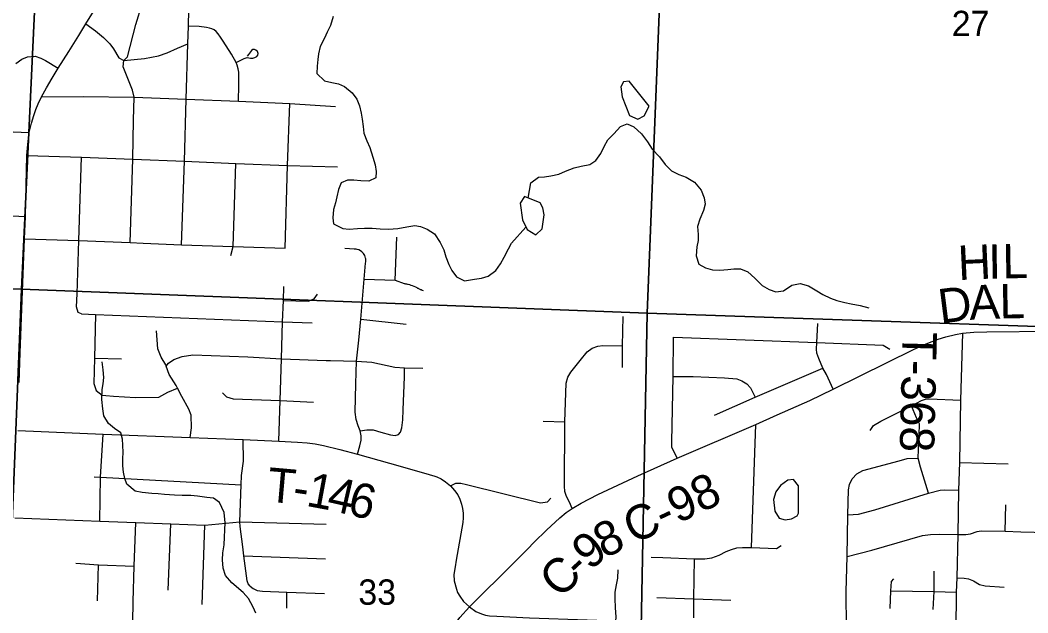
# Model space of a CAD drawing. Extents: x 0 to 34, y 0 to 22.
# Drawn here: x 5.169 to 6.833, y 15.396 to 16.375 of the extents above; entities that cross this region are included whole.
import ezdxf

# ---------------------------------------------------------------- set-up
doc = ezdxf.new("R2010")
doc.units = 0
for name, color, linetype in [('GM_X_Corporation', 7, 'Continuous'), ('GM_X_County_Road', 7, 'Continuous'), ('GM_X_County_Road_Text', 7, 'Continuous'), ('GM_X_Minor_Lake', 7, 'Continuous'), ('GM_X_Minor_River', 7, 'Continuous'), ('GM_X_Section_Text', 7, 'Continuous'), ('GM_X_State_Route', 7, 'Continuous'), ('GM_X_Township_Road', 7, 'Continuous'), ('GM_X_Township_Road_Text', 7, 'Continuous')]:
    doc.layers.add(name, color=color, linetype=linetype)

msp = doc.modelspace()

# ---------------------------------------------------------------- linework, layer by layer
at = {"layer": 'GM_X_Corporation'}
for points in [[(5.2034, 16.9522), (5.1967, 16.4715), (5.1712, 15.9307), (4.1402, 15.964), (4.1823, 16.9818)], [(5.2034, 16.9522), (6.2453, 16.9071), (6.2042, 15.8911), (5.1712, 15.9307), (5.1967, 16.4715)], [(6.2453, 16.9071), (7.2756, 16.8704), (7.2356, 15.8559), (6.2042, 15.8911)], [(4.1402, 15.964), (5.1712, 15.9307), (5.1298, 14.9148), (4.1106, 14.9455)], [(5.1712, 15.9307), (6.2042, 15.8911), (6.1854, 14.88), (5.1298, 14.9148)], [(6.2042, 15.8911), (7.2356, 15.8559), (7.2089, 14.8416), (6.1854, 14.88)]]:
    msp.add_lwpolyline(points, close=True, dxfattribs=at)
at = {"layer": 'GM_X_County_Road'}
for points in [[(6.0179, 15.5128), (6.0381, 15.533), (6.0601, 15.5533), (6.0709, 15.562), (6.0807, 15.5687), (6.0954, 15.5774), (6.1227, 15.5914), (6.1891, 15.6225), (6.2539, 15.6514), (6.384, 15.7073), (6.419, 15.723), (6.4731, 15.7469), (6.5116, 15.7654), (6.6441, 15.8309), (6.6651, 15.8404), (6.6847, 15.8483), (6.6979, 15.8522), (6.7138, 15.8561), (6.7251, 15.858), (6.7436, 15.8597), (6.7654, 15.8605), (6.8727, 15.8614)], [(5.6145, 15.1191), (5.6175, 15.1203), (5.6338, 15.126), (5.6814, 15.1424), (5.732, 15.1595), (5.7488, 15.1661), (5.7643, 15.1736), (5.7818, 15.1854), (5.7952, 15.1976), (5.8068, 15.212), (5.8129, 15.2215), (5.8193, 15.2329), (5.8302, 15.2613), (5.8476, 15.3063), (5.856, 15.3274), (5.865, 15.3452), (5.879, 15.367), (5.8949, 15.3886), (5.9111, 15.406), (5.9846, 15.4793), (6.0068, 15.5016), (6.0179, 15.5128)], [(5.9111, 15.406), (5.9217, 15.3983), (5.931, 15.3945), (5.9376, 15.3927), (5.9443, 15.3913), (5.9561, 15.3908), (6.0101, 15.3883), (6.2004, 15.3814), (6.2816, 15.3786), (6.4091, 15.3749), (6.5336, 15.3708), (6.6147, 15.3683), (6.6506, 15.3674), (6.6923, 15.3658), (6.7048, 15.3649), (6.7136, 15.3641), (6.7227, 15.3622), (6.7349, 15.3585), (6.761, 15.3495), (6.8267, 15.3266), (6.891, 15.3044)]]:
    msp.add_lwpolyline(points, dxfattribs=at)
at = {"layer": 'GM_X_Minor_Lake'}
for points in [[(6.1747, 16.274), (6.1652, 16.2731), (6.1611, 16.2647), (6.1629, 16.2484), (6.1754, 16.2174), (6.1892, 16.2111), (6.1997, 16.2166), (6.2079, 16.2327)], [(6.2079, 16.2327), (6.1747, 16.274)], [(6.0016, 16.0835), (5.9946, 16.0728), (5.9983, 16.0451), (6.0062, 16.0292), (6.0203, 16.0203), (6.0308, 16.0303), (6.0343, 16.0536), (6.0322, 16.0649), (6.0276, 16.0732)], [(6.0276, 16.0732), (6.0016, 16.0835)], [(6.4542, 15.6062), (6.4461, 15.6167), (6.4366, 15.6154), (6.4246, 15.6065), (6.4168, 15.5962), (6.4132, 15.5836), (6.415, 15.5639), (6.4223, 15.5526), (6.4322, 15.55), (6.4428, 15.5517), (6.4519, 15.5564), (6.4545, 15.561)], [(6.4545, 15.561), (6.4542, 15.6062)]]:
    msp.add_lwpolyline(points, dxfattribs=at)
at = {"layer": 'GM_X_Minor_River'}
for points in [[(5.6858, 16.3807), (5.6814, 16.3662), (5.6762, 16.3552), (5.6718, 16.3452), (5.6644, 16.3314), (5.6616, 16.3192), (5.6605, 16.3097), (5.6592, 16.2991), (5.659, 16.2869), (5.6716, 16.2749), (5.6838, 16.2717), (5.6945, 16.2699), (5.7044, 16.2651), (5.7171, 16.255), (5.7252, 16.2441), (5.7291, 16.2332), (5.7319, 16.2214), (5.7336, 16.2116), (5.7353, 16.1991), (5.7366, 16.1881), (5.7413, 16.1756), (5.7467, 16.1643), (5.7515, 16.1484), (5.7551, 16.1359), (5.7568, 16.1249), (5.7561, 16.1146), (5.7445, 16.1091), (5.7315, 16.1097), (5.7202, 16.1107), (5.7095, 16.1109), (5.699, 16.1062), (5.6949, 16.0955), (5.6917, 16.083), (5.6896, 16.073), (5.6863, 16.0624), (5.6853, 16.0483), (5.6862, 16.0384), (5.7019, 16.031), (5.7125, 16.0297), (5.7258, 16.0306), (5.7375, 16.0315), (5.7501, 16.0313), (5.7637, 16.0304), (5.777, 16.0298), (5.7926, 16.0308), (5.8073, 16.0337), (5.8206, 16.0358), (5.8301, 16.0344), (5.8411, 16.0296), (5.853, 16.0218), (5.8627, 16.0078), (5.8685, 15.9954), (5.8717, 15.984), (5.8768, 15.9716), (5.8819, 15.9614), (5.8896, 15.9509), (5.903, 15.9442), (5.9193, 15.9471), (5.9306, 15.9491), (5.942, 15.952), (5.9547, 15.9616), (5.9622, 15.9724), (5.9685, 15.9835), (5.9755, 15.9973), (5.9803, 16.0068), (6.0043, 16.033)], [(6.0078, 16.081), (6.0123, 16.1061), (6.0251, 16.1158), (6.0349, 16.1163), (6.0455, 16.1176), (6.0588, 16.1208), (6.0697, 16.1255), (6.0841, 16.131), (6.0954, 16.1335), (6.1098, 16.1367), (6.1195, 16.1433), (6.1277, 16.1548), (6.1336, 16.1663), (6.1396, 16.177), (6.1493, 16.187), (6.1605, 16.199), (6.1715, 16.2037), (6.1825, 16.1989), (6.1948, 16.1873), (6.2052, 16.1741), (6.2126, 16.1617), (6.2246, 16.149), (6.2342, 16.1365), (6.2446, 16.1261), (6.2568, 16.1201), (6.2686, 16.1154), (6.2828, 16.1072), (6.2936, 16.0944), (6.2983, 16.0816), (6.3, 16.071), (6.2974, 16.0603), (6.2912, 16.0465), (6.2876, 16.034), (6.2889, 16.0207), (6.2886, 16.0108), (6.2865, 16.0005), (6.2856, 15.9857), (6.2899, 15.9721), (6.301, 15.9658), (6.3124, 15.9625), (6.3242, 15.9623), (6.3375, 15.9632), (6.3477, 15.9645), (6.3583, 15.9643), (6.3709, 15.9595), (6.382, 15.949), (6.3943, 15.9367), (6.4058, 15.9304), (6.4169, 15.9263), (6.4294, 15.928), (6.4433, 15.9374), (6.4569, 15.9398), (6.471, 15.9362), (6.4844, 15.9277), (6.4947, 15.9221), (6.5073, 15.9158), (6.5176, 15.9122), (6.5309, 15.9086), (6.5412, 15.9064), (6.556, 15.9036), (6.5705, 15.9)], [(5.3379, 15.6828), (5.3351, 15.6934), (5.3247, 15.7009), (5.3148, 15.7087), (5.3074, 15.7215), (5.3053, 15.7333), (5.304, 15.7485), (5.3045, 15.7648), (5.3059, 15.7743), (5.3069, 15.785), (5.306, 15.7975), (5.3043, 15.8108)], [(5.558, 15.3957), (5.5537, 15.4059), (5.5463, 15.4198), (5.5371, 15.4299), (5.5186, 15.4456), (5.5079, 15.458), (5.5043, 15.4701), (5.5033, 15.4838), (5.5036, 15.4956), (5.5057, 15.5085), (5.5066, 15.5215), (5.5072, 15.5336), (5.5074, 15.545), (5.5057, 15.5617), (5.4983, 15.5783), (5.4883, 15.5854), (5.4773, 15.5868), (5.4621, 15.5888), (5.4507, 15.5898), (5.4363, 15.59), (5.4237, 15.5906), (5.4074, 15.5919), (5.3968, 15.5925), (5.3865, 15.5935), (5.3702, 15.5948), (5.3588, 15.5973), (5.3453, 15.6085), (5.3418, 15.6183), (5.3394, 15.6285), (5.3385, 15.6392), (5.3387, 15.6513), (5.3389, 15.6612), (5.3388, 15.673), (5.3379, 15.6828)], [(6.1557, 15.4671), (6.1555, 15.4534), (6.153, 15.4428), (6.1509, 15.4302), (6.151, 15.4196), (6.1516, 15.4051), (6.1529, 15.3892), (6.1516, 15.3774), (6.1449, 15.3655), (6.139, 15.3552), (6.1338, 15.3449), (6.1268, 15.3296), (6.122, 15.3189), (6.1165, 15.3078), (6.1075, 15.2947), (6.102, 15.2829)]]:
    msp.add_lwpolyline(points, dxfattribs=at)
at = {"layer": 'GM_X_State_Route'}
for points in [[(5.2042, 16.248), (5.2124, 16.2632), (5.2218, 16.279), (5.232, 16.2955), (5.2494, 16.3232), (5.2656, 16.3495), (5.2775, 16.3685), (5.2957, 16.3977), (5.3131, 16.4252)], [(5.184, 16.1896), (5.1875, 16.2049), (5.1913, 16.2175), (5.1948, 16.2275), (5.1987, 16.2366), (5.2042, 16.248)], [(5.1676, 15.7767), (5.1692, 15.8253), (5.1762, 16.0139), (5.1776, 16.0509), (5.1788, 16.1018), (5.1802, 16.1511), (5.1815, 16.1697), (5.184, 16.1896)]]:
    msp.add_lwpolyline(points, dxfattribs=at)
at = {"layer": 'GM_X_Township_Road'}
for p, q in [((5.7884, 15.9456), (5.7912, 16.0163)), ((5.7313, 15.8809), (5.8066, 15.873)), ((5.2918, 15.8169), (5.3362, 15.8157)), ((6.0328, 15.713), (6.0686, 15.7119)), ((6.3766, 15.5042), (6.384, 15.7073)), ((6.7201, 15.6445), (6.8007, 15.6421)), ((6.7956, 15.5311), (6.7965, 15.5746)), ((5.4134, 15.4336), (5.4176, 15.543)), ((5.4697, 15.4103), (5.4737, 15.5412)), ((5.5386, 15.4905), (5.6732, 15.4857)), ((5.2966, 15.4163), (5.2982, 15.4757)), ((5.6091, 15.4039), (5.6094, 15.4303))]:
    msp.add_line(p, q, dxfattribs=at)
for points in [[(5.3507, 16.0076), (5.3553, 16.1451), (5.3563, 16.2096), (5.3572, 16.2474), (5.3546, 16.2591), (5.3391, 16.298), (5.34, 16.3082), (5.3463, 16.3143), (5.3602, 16.3677), (5.3704, 16.4019), (5.3755, 16.4227)], [(5.4354, 16.004), (5.4403, 16.1421), (5.443, 16.2442), (5.4461, 16.336), (5.4472, 16.365), (5.4481, 16.4191)], [(5.2775, 16.3685), (5.2932, 16.3573), (5.3066, 16.346), (5.3168, 16.3358), (5.3232, 16.3275), (5.3319, 16.3124), (5.34, 16.3082), (5.3744, 16.3117), (5.3973, 16.3158), (5.4116, 16.3207), (5.4288, 16.3288), (5.4461, 16.336)], [(5.5295, 16.2411), (5.5299, 16.2674), (5.5299, 16.2836), (5.5299, 16.289), (5.529, 16.2943), (5.5275, 16.3003), (5.5257, 16.3048), (5.5181, 16.3184), (5.5043, 16.3402), (5.4998, 16.3467), (5.4958, 16.352), (5.4925, 16.356), (5.4894, 16.3587), (5.4856, 16.3607), (5.4818, 16.3618), (5.4767, 16.3627), (5.4646, 16.3643), (5.4472, 16.365)], [(5.5257, 16.3048), (5.5391, 16.3113), (5.544, 16.3133), (5.5493, 16.3121), (5.5531, 16.3121), (5.5564, 16.313), (5.5598, 16.315), (5.5616, 16.3168), (5.5622, 16.3195), (5.5609, 16.3228), (5.5582, 16.3255), (5.5558, 16.3266), (5.5533, 16.3262), (5.5511, 16.3246), (5.546, 16.3182), (5.5437, 16.3155)], [(5.1619, 16.3032), (5.1718, 16.3106), (5.1813, 16.3145), (5.1937, 16.3154), (5.2029, 16.3123), (5.211, 16.3084), (5.232, 16.2955)], [(5.184, 16.1896), (5.1875, 16.2049), (5.1913, 16.2175), (5.1948, 16.2275), (5.1987, 16.2366), (5.2042, 16.248)], [(5.2042, 16.248), (5.273, 16.2486), (5.3572, 16.2474), (5.443, 16.2442), (5.5295, 16.2411), (5.6142, 16.2373), (5.6898, 16.2323)], [(5.6066, 15.9982), (5.6105, 16.1348), (5.6142, 16.2373)], [(4.8845, 16.1241), (4.905, 16.1424), (4.916, 16.1538), (4.9265, 16.1653), (4.951, 16.1905), (4.955, 16.1972), (4.9619, 16.1976), (4.9689, 16.1973), (5.0315, 16.1959), (5.1039, 16.1925), (5.184, 16.1896)], [(5.1802, 16.1511), (5.27, 16.1484), (5.3553, 16.1451), (5.4403, 16.1421), (5.5251, 16.1383), (5.6105, 16.1348), (5.693, 16.1327)], [(5.2629, 15.9231), (5.2661, 16.0108), (5.27, 16.1484)], [(5.5167, 15.9863), (5.5206, 16.0011), (5.5251, 16.1383)], [(4.1199, 16.0878), (4.1661, 16.0886), (4.1847, 16.088), (4.2029, 16.0866), (4.2216, 16.0857), (4.2477, 16.0847), (4.2773, 16.084), (4.3004, 16.0838), (4.3544, 16.0828), (4.3818, 16.0818), (4.4203, 16.08), (4.454, 16.0785), (4.5131, 16.0767), (4.6153, 16.0736), (4.6616, 16.0717), (4.7043, 16.07), (4.736, 16.0686), (4.7389, 16.0685), (4.871, 16.0627), (4.9372, 16.0603), (5.0261, 16.0572), (5.1006, 16.0545), (5.1776, 16.0509)], [(5.1762, 16.0139), (5.2661, 16.0108), (5.3507, 16.0076), (5.3722, 16.0066)], [(5.3722, 16.0066), (5.4354, 16.004), (5.5206, 16.0011), (5.6066, 15.9982)], [(5.7261, 15.6583), (5.7299, 15.672), (5.7319, 15.6813), (5.7321, 15.6883), (5.7307, 15.697), (5.727, 15.7051), (5.7236, 15.7156), (5.722, 15.7276), (5.7235, 15.7745), (5.7246, 15.8118), (5.7283, 15.8464), (5.7313, 15.8809), (5.7371, 15.947), (5.7394, 15.9738), (5.7398, 15.9757), (5.7399, 15.9775), (5.7399, 15.9791), (5.7397, 15.9808), (5.7394, 15.9821), (5.7389, 15.9842), (5.738, 15.9862), (5.7371, 15.9879), (5.736, 15.9895), (5.7349, 15.9907), (5.7333, 15.9923), (5.731, 15.994), (5.7283, 15.9954), (5.7257, 15.9961), (5.7236, 15.9965), (5.7207, 15.9969), (5.7049, 15.9979)], [(5.7371, 15.947), (5.7884, 15.9456), (5.803, 15.94), (5.8042, 15.9399), (5.8054, 15.9397), (5.8068, 15.9394), (5.8085, 15.9391), (5.8099, 15.9388), (5.8121, 15.9382), (5.8143, 15.9375), (5.8166, 15.9367), (5.8191, 15.9356), (5.8216, 15.9345), (5.8239, 15.9332), (5.8245, 15.9329), (5.8252, 15.9325), (5.8261, 15.9321), (5.827, 15.9316), (5.828, 15.9312), (5.8289, 15.9308), (5.8298, 15.9304), (5.8311, 15.9299), (5.8329, 15.9292), (5.8346, 15.9287)], [(5.5959, 15.68), (5.5981, 15.7466), (5.6006, 15.8159), (5.6022, 15.877), (5.6037, 15.9118), (5.6043, 15.9352)], [(5.2704, 15.8899), (5.2647, 15.892), (5.2621, 15.9015), (5.2629, 15.9231)], [(5.6037, 15.9118), (5.6447, 15.9107), (5.6544, 15.9148), (5.6599, 15.9224)], [(5.2704, 15.8899), (5.2935, 15.8889), (5.6022, 15.877), (5.6511, 15.8751)], [(5.2935, 15.8889), (5.2918, 15.8169), (5.2905, 15.7749), (5.2945, 15.7633), (5.3045, 15.7554), (5.3105, 15.7551), (5.3232, 15.7541), (5.3592, 15.752), (5.3982, 15.7522), (5.413, 15.7604), (5.4288, 15.767)], [(6.1639, 15.8015), (6.1636, 15.8371), (6.165, 15.8853)], [(5.4499, 15.6856), (5.4519, 15.7019), (5.4512, 15.7228), (5.4474, 15.7326), (5.4362, 15.7532), (5.4288, 15.767), (5.4264, 15.7714), (5.4151, 15.79), (5.4103, 15.8037), (5.4095, 15.8059), (5.402, 15.8185), (5.3964, 15.8322), (5.3943, 15.8619)], [(6.5116, 15.7654), (6.5004, 15.79), (6.4947, 15.8001), (6.4877, 15.8161), (6.4847, 15.8248), (6.4841, 15.8315), (6.4847, 15.8424), (6.4861, 15.8738)], [(6.2539, 15.6514), (6.2451, 15.6698), (6.2449, 15.6785), (6.2471, 15.7867), (6.2477, 15.8516)], [(6.2477, 15.8516), (6.4847, 15.8424), (6.5939, 15.8382), (6.6054, 15.8318)], [(6.7251, 15.858), (6.722, 15.7474), (6.7201, 15.6445), (6.7187, 15.5989), (6.7172, 15.5257), (6.7156, 15.4542), (6.7149, 15.4305), (6.7145, 15.4107), (6.7136, 15.3641)], [(6.0807, 15.5687), (6.0762, 15.5788), (6.0714, 15.5886), (6.0686, 15.5967), (6.0678, 15.6057), (6.0686, 15.7119), (6.0709, 15.7757), (6.0734, 15.7855), (6.0782, 15.7939), (6.0936, 15.8127), (6.1056, 15.827), (6.1135, 15.8334), (6.123, 15.8365), (6.1314, 15.8374), (6.1636, 15.8371)], [(5.4103, 15.8037), (5.4138, 15.8083), (5.4227, 15.8144), (5.4364, 15.8197), (5.4539, 15.822), (5.545, 15.8189), (5.6006, 15.8159), (5.6744, 15.813), (5.6816, 15.8128)], [(5.6816, 15.8128), (5.7246, 15.8118), (5.75, 15.8099), (5.7878, 15.8018), (5.8036, 15.801), (5.8342, 15.8002)], [(5.7307, 15.697), (5.7414, 15.6987), (5.7517, 15.6982), (5.7647, 15.6947), (5.7807, 15.6902), (5.7882, 15.689), (5.7938, 15.6908), (5.7969, 15.6945), (5.7991, 15.7015), (5.8009, 15.7151), (5.8016, 15.7315), (5.8034, 15.786), (5.8036, 15.801)], [(6.3157, 15.7225), (6.3827, 15.7525), (6.4947, 15.8001)], [(6.2471, 15.7867), (6.2802, 15.7864), (6.3323, 15.7841), (6.3527, 15.7827), (6.3606, 15.7796), (6.3692, 15.7746), (6.3748, 15.7679), (6.3827, 15.7525)], [(5.5032, 15.7593), (5.5097, 15.7528), (5.5209, 15.7494), (5.5981, 15.7466), (5.6532, 15.7441)], [(6.5724, 15.6976), (6.578, 15.7057), (6.5903, 15.713), (6.641, 15.7379), (6.6575, 15.7469), (6.6642, 15.7491), (6.6707, 15.7494), (6.722, 15.7474)], [(6.669, 15.5936), (6.6556, 15.6368), (6.6522, 15.6519), (6.6536, 15.6945), (6.6542, 15.7032), (6.6539, 15.7085), (6.6494, 15.7183), (6.641, 15.7379)], [(5.165, 15.6974), (5.306, 15.6914), (5.4499, 15.6856), (5.537, 15.6824), (5.5959, 15.68), (5.6271, 15.6783), (5.6432, 15.677), (5.6561, 15.6753), (5.67, 15.6728), (5.6971, 15.6662), (5.7261, 15.6583), (5.7965, 15.6385), (5.8445, 15.6248), (5.854, 15.6217)], [(5.3004, 15.5478), (5.3018, 15.6204), (5.306, 15.6914)], [(5.5488, 15.4406), (5.5453, 15.4443), (5.5436, 15.4493), (5.5386, 15.4905), (5.5365, 15.5055), (5.5325, 15.5388), (5.532, 15.5466), (5.5339, 15.6078), (5.5347, 15.6228), (5.5379, 15.6466), (5.537, 15.6824)], [(6.5336, 15.3708), (6.5331, 15.4317), (6.5348, 15.4894), (6.5359, 15.5583), (6.5368, 15.5992), (6.5385, 15.6082), (6.5429, 15.6177), (6.5505, 15.6258), (6.5606, 15.6314), (6.6203, 15.6474), (6.634, 15.6513), (6.6522, 15.6519)], [(5.2912, 15.621), (5.3018, 15.6204), (5.5339, 15.6078)], [(5.854, 15.6217), (5.8569, 15.6208), (5.8643, 15.6173), (5.8714, 15.6128), (5.8798, 15.6062), (5.8863, 15.5985), (5.8915, 15.5909), (5.8951, 15.5841), (5.898, 15.5757), (5.8996, 15.5688), (5.9006, 15.5606), (5.9006, 15.5529), (5.8998, 15.5454), (5.8892, 15.4835), (5.8871, 15.4721), (5.8853, 15.4596), (5.8859, 15.449), (5.8895, 15.4354), (5.8914, 15.4299), (5.8949, 15.4238), (5.9012, 15.4148), (5.9111, 15.406)], [(5.8798, 15.6062), (5.8886, 15.6103), (5.8967, 15.6105), (5.9059, 15.6084), (6.0285, 15.5777), (6.0397, 15.5797), (6.0455, 15.5858)], [(6.5359, 15.5583), (6.5533, 15.5592), (6.5802, 15.5665), (6.669, 15.5936), (6.6881, 15.5989), (6.6962, 15.5992), (6.7187, 15.5989)], [(5.16, 15.5533), (5.3004, 15.5478), (5.3601, 15.5455), (5.4176, 15.543), (5.4737, 15.5412), (5.532, 15.5466), (5.6741, 15.5427)], [(5.3557, 15.4149), (5.3573, 15.4734), (5.3601, 15.5455)], [(6.5348, 15.4894), (6.5752, 15.4995), (6.6592, 15.5241), (6.6721, 15.5258), (6.6872, 15.5264), (6.7172, 15.5257), (6.7304, 15.5256), (6.7384, 15.5268), (6.7496, 15.5307), (6.7562, 15.5316), (6.7956, 15.5311), (6.8213, 15.5301), (6.8882, 15.5284)], [(6.2112, 15.4883), (6.2303, 15.4874), (6.2825, 15.4856), (6.2996, 15.4855), (6.3113, 15.4871), (6.3234, 15.4913), (6.3347, 15.4975), (6.3439, 15.5011), (6.3523, 15.5036), (6.3621, 15.504), (6.3766, 15.5042), (6.4182, 15.5023), (6.4259, 15.5076)], [(5.2609, 15.4783), (5.2982, 15.4757), (5.3573, 15.4734)], [(6.2816, 15.3883), (6.2816, 15.4192), (6.2825, 15.4856)], [(6.6769, 15.4018), (6.6781, 15.4313), (6.6785, 15.4652)], [(6.6057, 15.4037), (6.6066, 15.4328), (6.608, 15.4481), (6.6116, 15.4526)], [(6.7156, 15.4542), (6.7277, 15.4535), (6.7352, 15.4523), (6.7434, 15.4493), (6.7535, 15.4432), (6.7628, 15.4407), (6.7939, 15.4389)], [(5.5488, 15.4406), (5.5536, 15.4364), (5.5605, 15.4332), (5.569, 15.4323), (5.6094, 15.4303), (5.6718, 15.4284)], [(6.6066, 15.4328), (6.6781, 15.4313), (6.7149, 15.4305)], [(5.3521, 15.3754), (5.3548, 15.3806), (5.3557, 15.4149)], [(6.2205, 15.4217), (6.2816, 15.4192), (6.3428, 15.4171)]]:
    msp.add_lwpolyline(points, dxfattribs=at)

# ---------------------------------------------------------------- texts
at = {"layer": 'GM_X_County_Road_Text'}
for s, height, rotation, p in [('H', 0.0568, 2.6674, (6.7187, 15.9456)), ('I', 0.0568, 1.0226, (6.7682, 15.9479)), ('L', 0.0568, 1.02, (6.7915, 15.9484)), ('D', 0.0568, 7.2321, (6.6888, 15.8737)), ('A', 0.0568, 2.6237, (6.7372, 15.8799)), ('L', 0.0568, 1.0286, (6.7867, 15.8822)), ('C-98', 0.05682, 25.1224, (6.1821, 15.5091)), ('8', 0.0568, 26.4287, (6.1338, 15.4853)), ('9', 0.0568, 38.9475, (6.1096, 15.4652)), ('C', 0.0568, 43.9571, (6.0603, 15.4182)), ('-', 0.0568, 42.8281, (6.0934, 15.4502))]:
    msp.add_text(s, height=height, rotation=rotation, dxfattribs=at).set_placement(p)
at = {"layer": 'GM_X_Section_Text'}
for s, p in [('27', (6.7074, 16.3484)), ('33', (5.7274, 15.4096))]:
    msp.add_text(s, height=0.04186, rotation=0, dxfattribs=at).set_placement(p)
at = {"layer": 'GM_X_Township_Road_Text'}
for s, height, rotation, p in [('T-368', 0.05682, 268.5957, (6.6263, 15.8607)), ('T', 0.0568, 355.0139, (5.5756, 15.58)), ('1', 0.0568, 349.3963, (5.6396, 15.5732)), ('4', 0.0568, 347.1528, (5.6734, 15.5669)), ('6', 0.0568, 346.2768, (5.7073, 15.5592)), ('-', 0.0568, 351.8854, (5.6171, 15.5764))]:
    msp.add_text(s, height=height, rotation=rotation, dxfattribs=at).set_placement(p)

doc.saveas('drawing.dxf')
